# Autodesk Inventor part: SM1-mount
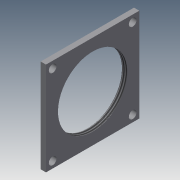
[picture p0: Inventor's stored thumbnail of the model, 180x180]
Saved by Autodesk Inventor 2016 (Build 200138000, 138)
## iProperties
Created: 2014-08
Part Number: SM1-mount
Material: Generic
Document SubType Name: Modeling
Designer: James
Density: 1 g/cm^3
Appearance: Default
Author: James
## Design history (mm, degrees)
sketch "Sketch1"
  geometry: L1 (34.536, -28.597)-(-0.464, -28.597); L2 (-0.464, -28.597)-(-0.464, 6.403); L3 (-0.464, 6.403)-(34.536, 6.403); L4 (34.536, 6.403)-(34.536, -28.597); L5 (34.536, -28.597)-(-0.464, 6.403); L6 (-0.464, -28.597)-(34.536, 6.403); 2 further points
  constraints: 12 end point, 2 midpoint, 2 parallel, 1 horizontal, 1 perpendicular
  dimensions: "d2" = 35 distance between parallel lines of L1 L3; "d3" = 35 distance between parallel lines of L2 L4
extrude "Extrusion1" new body sketch "Sketch1" distance "d0" = 2; taper "d1" = 0 deg
sketch "Sketch2"
  geometry: L1 (28.597, -0.464)-(28.597, 34.536) reference; L2 (28.597, 34.536)-(-6.403, 34.536) reference; L3 (-6.403, 34.536)-(-6.403, -0.464) reference; L4 (-6.403, -0.464)-(28.597, -0.464) reference; 5 further points
  dimensions: "d4" = 2.5 distance from line of L3 point (-3.903, 2.036); "d5" = 2.5 distance from line of L4 point (-3.903, 2.036) (= d4); "d6" = 2.5 distance from line of L3 point (-3.903, 32.036) (= d4); "d7" = 2.5 distance from line of L2 point (-3.903, 32.036) (= d4); "d8" = 2.5 distance from line of L2 point (26.097, 32.036) (= d4); "d9" = 2.5 distance from line of L1 point (26.097, 32.036) (= d4); "d10" = 2.5 distance from line of L1 point (26.097, 2.036) (= d4); "d11" = 2.5 distance from line of L4 point (26.097, 2.036) (= d4)
hole "Hole1" sketch "Sketch2" at (-3.903, 32.036), (26.097, 32.036), (26.097, 2.036), (-3.903, 2.036) diameter "d12" = 2.9; stored, may be unused: countersink angle "d16" = 90 deg, drill point angle "d18" = 118 deg; dims "d13" = 6, "d14" = 5.5, "d15" = 2, "d17" = 8
sketch "Sketch3"
  geometry: 2 further points
hole "Hole2" sketch "Sketch3" at (11.097, 17.036) diameter "d19" = 26.01; stored, may be unused: countersink angle "d23" = 90 deg, drill point angle "d25" = 118 deg; dims "d20" = 6, "d21" = 5.5, "d22" = 2, "d24" = 8
body "Solid1"
